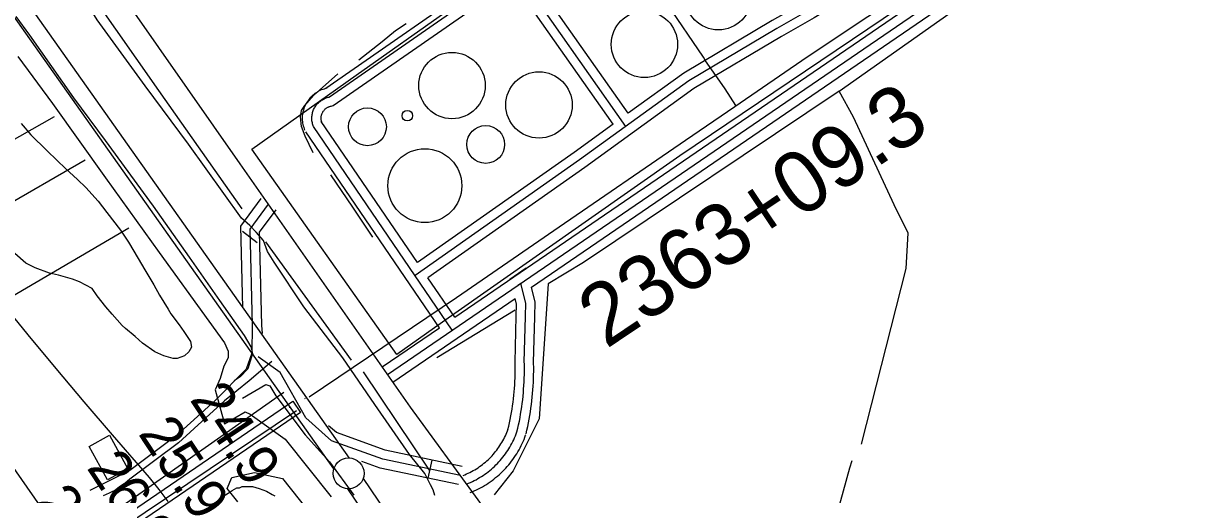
# Model space of a CAD drawing. Extents: x 3355724 to 3393621, y 594744 to 620174.
# Drawn here: x 3384041 to 3385918, y 610441 to 611204 of the extents above; entities that cross this region are included whole.
import ezdxf

# ---------------------------------------------------------------- set-up
doc = ezdxf.new("R2010")
doc.units = 0
for name, color, linetype in [('V-BLDG-OTLN', 7, 'Continuous'), ('V-CHAN-DOCK', 7, 'Continuous'), ('V-DOMW-TANK', 7, 'Continuous'), ('V-FLOD-BASE', 7, 'Continuous'), ('V-LEVE-TOET', 7, 'Continuous'), ('V-RIVR-EDGE', 7, 'Continuous'), ('V-RIVR-RANG', 7, 'Continuous'), ('V-ROAD-CNTR', 7, 'Continuous'), ('V-SITE-OTLN', 7, 'Continuous'), ('V-SITE-VEGE', 7, 'Continuous'), ('V-SURV-IDEN', 7, 'Continuous'), ('V-SURV-LINE', 7, 'Continuous'), ('V-TOPO-MAJR', 7, 'Continuous'), ('V-TOPO-SHOR', 7, 'Continuous'), ('V-UTIL-LINE', 7, 'Continuous'), ('V-WETL-SWMP', 7, 'Continuous')]:
    doc.layers.add(name, color=color, linetype=linetype)

msp = doc.modelspace()

# ---------------------------------------------------------------- linework, layer by layer
at = {"layer": 'V-BLDG-OTLN'}
msp.add_lwpolyline([(3384181, 610537.4), (3384210.7, 610483.3), (3384177.6, 610465.1), (3384147.9, 610519.2)], close=True, dxfattribs=at)
at = {"layer": 'V-CHAN-DOCK'}
msp.add_lwpolyline([(3383879.4, 610186.2), (3383922.8, 610214.2), (3383886.5, 610267.4), (3383918.5, 610289.2), (3383955.1, 610235.7), (3384477.5, 610592.5), (3384489.9, 610574.3), (3383836, 610127.7), (3383918.8, 610006.3), (3383927, 610011.9), (3383938.6, 609994.9), (3383928.7, 609988.1), (3383959.9, 609942.4), (3383971, 609950), (3384010.8, 609891.8), (3383999.7, 609884.3)], dxfattribs=at)
at = {"layer": 'V-DOMW-TANK'}
for centre, radius in [((3385165.5, 611247.4), 53.7), ((3385045.9, 611170.2), 53.7), ((3384734.8, 611103.6), 53.7), ((3384875.5, 611072.1), 53.7), ((3384598.1, 611036.8), 30.6), ((3384662.6, 611054.8), 8.61), ((3384789.3, 611008.2), 30.6), ((3384690.9, 610941.5), 59.8)]:
    msp.add_circle(centre, radius, dxfattribs=at)
at = {"layer": 'V-FLOD-BASE'}
for points in [[(3384029.3, 611215.1), (3384051.4, 611185), (3384122.6, 611083.5), (3384174.2, 611014.5), (3384251.5, 610908.4), (3384310, 610825.8), (3384358.7, 610755.7), (3384398.8, 610699.1), (3384409.4, 610680.5), (3384412.3, 610669.8), (3384404.7, 610644.8), (3384392.3, 610632.1), (3384382.4, 610625.5)], [(3384395.9, 610597.5), (3384433.9, 610619.9), (3384440.4, 610617.4), (3384449.8, 610601.4), (3384497.3, 610538.2), (3384536.6, 610494.4), (3384575.9, 610440.3)]]:
    msp.add_lwpolyline(points, dxfattribs=at)
at = {"layer": 'V-LEVE-TOET'}
msp.add_line((3384351.7, 610611.2), (3384366.8, 610555.8), dxfattribs=at)
for points in [[(3384706.9, 610439.9), (3384704.2, 610449.3), (3384699.8, 610457.5), (3384691.1, 610475.6), (3384666.1, 610506.4), (3384610, 610587.1), (3384558.3, 610662.9), (3384495.2, 610745.2), (3384447.3, 610817.7), (3384436.4, 610834.7), (3384429.9, 610852.8), (3384417.9, 610866), (3384408.1, 610877), (3384394.5, 610889.1), (3384308.5, 611008.8), (3384238.8, 611103.3), (3384160.9, 611209.9), (3384100.6, 611307.6), (3384038, 611388.9)], [(3384032.6, 611150.7), (3384088.7, 611074.4), (3384174.7, 610954.1), (3384261.2, 610833.3), (3384341.8, 610722.3), (3384366.8, 610687.2), (3384372.8, 610673.5), (3384372.7, 610663.1), (3384366.1, 610649.4), (3384360, 610629.2), (3384351.7, 610611.2)], [(3384366.8, 610555.8), (3384400.3, 610575.4), (3384408.5, 610571.5), (3384465.2, 610531.3), (3384539.3, 610437.9)]]:
    msp.add_lwpolyline(points, dxfattribs=at)
at = {"layer": 'V-RIVR-EDGE'}
msp.add_spline([(3384488, 609371.5), (3384468, 609400.3), (3384449.8, 609430.7), (3384446.7, 609441.6), (3384446.7, 609445.8), (3384449.8, 609449.4), (3384459, 609452.2), (3384462.2, 609453.6), (3384464.7, 609457.4), (3384464.7, 609462.4), (3384463.6, 609466.9), (3384459.8, 609472.2), (3384441.1, 609480.7), (3384422.5, 609488.9), (3384414.4, 609495.3), (3384408.7, 609501.6), (3384402.1, 609512.9), (3384392.3, 609532), (3384386.7, 609543.9), (3384376.1, 609562.3), (3384359.3, 609590.2), (3384337.5, 609625.5), (3384315.4, 609654.4), (3384293.6, 609688.7), (3384287.3, 609698.5), (3384283.8, 609710.9), (3384277.9, 609721.1), (3384265.6, 609738.4), (3384253.6, 609756.8), (3384246.6, 609768.1), (3384246.3, 609772.6), (3384246.3, 609776.5), (3384242.4, 609783.6), (3384235.1, 609798), (3384231.5, 609805.1), (3384224.9, 609816), (3384207.7, 609841.1), (3384198.5, 609854.5), (3384190.8, 609866.9), (3384180.7, 609885.2), (3384172.6, 609897.2), (3384163.8, 609910.6), (3384162.1, 609915.9), (3384159.6, 609926.1), (3384156.5, 609933.9), (3384148.7, 609945.9), (3384136.8, 609963.9), (3384088.7, 610023.2), (3384052.1, 610069.5), (3384015.3, 610119.2), (3383995.6, 610145.4), (3383986.1, 610157.7), (3383981.2, 610168.7), (3383979.1, 610182.8), (3383978.5, 610198.6), (3383977.8, 610206.7), (3383975.7, 610221.9), (3383972.6, 610238.4), (3383967.3, 610252.9), (3383958.9, 610271.6), (3383941, 610293.5), (3383922, 610309.8), (3383902.7, 610323.9), (3383894.2, 610334.8), (3383878.8, 610353.2), (3383873.5, 610361.7), (3383870.7, 610372.2), (3383868.3, 610388.1), (3383866.9, 610394.1), (3383863.4, 610403.3), (3383845.5, 610426.2), (3383823.3, 610446.4), (3383814.2, 610458.7), (3383797.7, 610478.8), (3383775.2, 610500.7), (3383748.1, 610529), (3383721.1, 610558.3), (3383710.5, 610571.7), (3383704.9, 610579.5), (3383693, 610606.3), (3383683.5, 610626.8), (3383664.6, 610666.6), (3383634.8, 610729.8), (3383616.2, 610766.1), (3383600.8, 610792.9)], degree=3, dxfattribs=at)
at = {"layer": 'V-ROAD-CNTR'}
for p, q in [((3384419.9, 610849.2), (3384395.8, 610867.1)), ((3384497, 610597.1), (3384497.8, 610597.5)), ((3384471.6, 610582.8), (3384472, 610583)), ((3384696.3, 610468.1), (3384702.5, 610497.4))]:
    msp.add_line(p, q, dxfattribs=at)
for points in [[(3385398.9, 609542.3), (3385133.9, 609925.7), (3385002.2, 610111.9), (3384892.4, 610269.5), (3384777.3, 610432.8), (3384667.5, 610583.2), (3384392.1, 610976.7), (3383958.2, 611597.8), (3383762.4, 611871.6), (3383538.2, 612187.4), (3383277.9, 612554.1), (3382922.5, 613059.3), (3382670, 613416.6), (3382435.3, 613754.7), (3382276.6, 613979.4), (3382102.9, 614235.8), (3381961, 614438.8), (3381786.9, 614698.7)], [(3384630.6, 610636), (3387016, 612269.2), (3387921, 612884.9), (3389025.3, 613640.7), (3389125.7, 613727.5)], [(3388670.9, 613535.3), (3385357.8, 611252.6), (3385313, 611226.2), (3385260.2, 611196), (3385117.8, 611111.2), (3384941.1, 610983.2), (3384675.1, 610796)], [(3384536.8, 611085.1), (3385903.8, 612036.2), (3386441.5, 612400), (3386654.5, 612543), (3387141, 612886.2)], [(3387329.9, 612593.1), (3385365.9, 611239.9), (3385320.6, 611213.2), (3385267.8, 611183.1), (3385126, 611098.6), (3384949.8, 610971), (3384695.8, 610792.3)], [(3384739.2, 610728.5), (3387007.5, 612281.6), (3387373.9, 612530.9)], [(3384863.1, 610777), (3387024.4, 612256.8), (3387396.9, 612510.2)], [(3384530.8, 611099.2), (3385077.4, 611479.5)], [(3385016.1, 611037.5), (3384836.5, 611293.6)], [(3385019.7, 611058.6), (3384857.5, 611289.9)], [(3384542.8, 611071), (3384832.8, 611272.8)], [(3384995.4, 611041), (3384832.8, 611272.8)], [(3385274.5, 611221.5), (3385252.6, 611209), (3385109.5, 611123.7), (3385019.7, 611058.6)], [(3384497, 611031.5), (3384496.3, 611033.4), (3384495.5, 611035.6), (3384494.8, 611037.9), (3384494.3, 611040.3), (3384493.8, 611042.6), (3384493.5, 611045), (3384493.3, 611047.4), (3384493.2, 611049.8), (3384493.2, 611052.1), (3384493.3, 611054.5), (3384493.6, 611056.9), (3384493.9, 611059.3), (3384494.4, 611061.6), (3384495, 611063.9), (3384495.7, 611066.2), (3384496.5, 611068.5), (3384497.4, 611070.7), (3384498.4, 611072.9), (3384499.5, 611075), (3384500.7, 611077), (3384502, 611079), (3384503.4, 611081), (3384504.9, 611082.8), (3384506.5, 611084.6), (3384508.2, 611086.4), (3384509.9, 611088), (3384511.8, 611089.5), (3384513.7, 611091), (3384515.6, 611092.4), (3384517.6, 611093.6), (3384519.7, 611094.8), (3384521.9, 611095.9), (3384524, 611096.9), (3384526.3, 611097.7), (3384528.5, 611098.5), (3384530.8, 611099.1), (3384533.1, 611099.6), (3384530.8, 611099.2)], [(3384511, 611037), (3384510.3, 611038.5), (3384509.8, 611040.1), (3384509.3, 611041.7), (3384509, 611043.4), (3384508.6, 611045), (3384508.4, 611046.7), (3384508.3, 611048.3), (3384508.2, 611050), (3384508.2, 611051.7), (3384508.3, 611053.4), (3384508.5, 611055), (3384508.7, 611056.7), (3384509, 611058.3), (3384509.5, 611060), (3384509.9, 611061.6), (3384510.5, 611063.1), (3384511.1, 611064.7), (3384511.8, 611066.2), (3384512.6, 611067.7), (3384513.5, 611069.1), (3384514.4, 611070.5), (3384515.4, 611071.9), (3384516.4, 611073.2), (3384517.5, 611074.4), (3384518.7, 611075.6), (3384519.9, 611076.8), (3384521.2, 611077.9), (3384522.5, 611078.9), (3384523.9, 611079.9), (3384525.3, 611080.7), (3384526.8, 611081.6), (3384528.3, 611082.3), (3384529.8, 611083), (3384531.4, 611083.6), (3384532.9, 611084.1), (3384534.6, 611084.6), (3384536.2, 611085), (3384536.8, 611085.1)], [(3384524.9, 611042.5), (3384524.4, 611043.7), (3384524.1, 611044.6), (3384523.9, 611045.5), (3384523.6, 611046.5), (3384523.5, 611047.4), (3384523.3, 611048.4), (3384523.2, 611049.3), (3384523.2, 611050.3), (3384523.2, 611051.2), (3384523.3, 611052.2), (3384523.4, 611053.1), (3384523.5, 611054.1), (3384523.7, 611055), (3384523.9, 611056), (3384524.2, 611056.9), (3384524.5, 611057.8), (3384524.9, 611058.7), (3384525.3, 611059.5), (3384525.7, 611060.4), (3384526.2, 611061.2), (3384526.7, 611062), (3384527.3, 611062.8), (3384527.9, 611063.5), (3384528.5, 611064.3), (3384529.2, 611064.9), (3384529.9, 611065.6), (3384530.6, 611066.2), (3384531.4, 611066.8), (3384532.2, 611067.3), (3384533, 611067.9), (3384533.8, 611068.3), (3384534.7, 611068.8), (3384535.6, 611069.1), (3384536.4, 611069.5), (3384537.4, 611069.8), (3384538.3, 611070.1), (3384539.3, 611070.3), (3384542.8, 611071)], [(3384678.9, 610817.1), (3384523.4, 611045.4)], [(3384714.4, 610711.6), (3384498.6, 611028.5)], [(3384735.3, 610707.6), (3384511, 611037)], [(3384995.4, 611041), (3384932.4, 610995.4), (3384678.9, 610817.1)], [(3384437.7, 610911.5), (3384407.8, 610871.3), (3384411.9, 610715.6), (3384410.9, 610670.4), (3384401.8, 610644.4), (3384351.6, 610593.8), (3384289.1, 610537.1), (3384214.1, 610480.7), (3384149.4, 610448.1)], [(3384425.7, 610920.5), (3384392.7, 610876.1), (3384396.2, 610744)], [(3384449.7, 610902.6), (3384422.9, 610866.5), (3384426.9, 610715.7), (3384427.6, 610702.1)], [(3384855, 610807.8), (3384828.2, 610789.5)], [(3384739.2, 610728.5), (3384695.8, 610792.3)], [(3384851.7, 610655.6), (3384853.8, 610729.7), (3384854.3, 610751.3), (3384845.9, 610783.4), (3384841.1, 610780.1)], [(3384866.7, 610655.2), (3384868.8, 610729.3), (3384869.4, 610753), (3384863.1, 610777)], [(3384639.1, 610623.6), (3384836.8, 610759)], [(3384836.7, 610656), (3384838.8, 610730.1), (3384839.3, 610749.5), (3384836.8, 610759)], [(3384622.1, 610648.3), (3384714.4, 610711.6)], [(3384443.3, 610657), (3384406.6, 610625.8), (3384367.1, 610593.1), (3384337, 610565.5), (3384292.3, 610525.5), (3384213.9, 610466.7), (3384210.2, 610463.2), (3384206.3, 610459.9), (3384202.2, 610456.7), (3384198.1, 610453.7), (3384193.8, 610450.9), (3384189.4, 610448.3), (3384184.8, 610445.8), (3384180.2, 610443.6), (3384175.5, 610441.5), (3384170.8, 610439.6)], [(3384748.4, 610472.5), (3384622.9, 610498.8), (3384540, 610528.6), (3384498.5, 610565.8), (3384456.9, 610639.3), (3384421.2, 610664.3)], [(3384825.3, 610546.6), (3384826.6, 610552.2), (3384827.8, 610557.7), (3384829, 610563.2), (3384830, 610568.8), (3384831, 610574.3), (3384831.9, 610579.9), (3384832.8, 610585.4), (3384833.5, 610591), (3384834.2, 610596.6), (3384834.8, 610602.2), (3384835.3, 610607.8), (3384835.8, 610613.4), (3384836.2, 610619), (3384836.5, 610624.6), (3384836.7, 610630.3), (3384836.8, 610635.9), (3384836.9, 610641.5), (3384836.9, 610647.2), (3384836.8, 610652.8), (3384836.7, 610655.2)], [(3384839.9, 610543.2), (3384841.2, 610548.9), (3384842.5, 610554.6), (3384843.7, 610560.3), (3384844.8, 610566), (3384845.8, 610571.8), (3384846.8, 610577.5), (3384847.6, 610583.3), (3384848.4, 610589.1), (3384849.1, 610594.9), (3384849.7, 610600.7), (3384850.3, 610606.5), (3384850.7, 610612.3), (3384851.1, 610618.1), (3384851.4, 610624), (3384851.7, 610629.8), (3384851.8, 610635.6), (3384851.9, 610641.5), (3384851.9, 610647.3), (3384851.8, 610653.1), (3384851.7, 610655.6)], [(3384854.5, 610539.8), (3384855.9, 610545.6), (3384857.2, 610551.5), (3384858.4, 610557.4), (3384859.5, 610563.3), (3384860.6, 610569.3), (3384861.6, 610575.2), (3384862.5, 610581.2), (3384863.3, 610587.2), (3384864, 610593.2), (3384864.7, 610599.2), (3384865.2, 610605.2), (3384865.7, 610611.2), (3384866.1, 610617.2), (3384866.4, 610623.3), (3384866.7, 610629.3), (3384866.8, 610635.3), (3384866.9, 610641.4), (3384866.9, 610647.4), (3384866.8, 610653.4), (3384866.7, 610656)], [(3384751.4, 610487.2), (3384627, 610513.3), (3384547.8, 610541.8), (3384535.3, 610552.9)], [(3384752.8, 610472.5), (3384755.8, 610473.7), (3384758.5, 610474.9), (3384761.2, 610476.2), (3384763.9, 610477.5), (3384766.6, 610478.9), (3384769.2, 610480.3), (3384771.8, 610481.8), (3384774.3, 610483.4), (3384776.9, 610485), (3384779.3, 610486.7), (3384781.8, 610488.5), (3384784.1, 610490.3), (3384786.5, 610492.1), (3384788.8, 610494), (3384791, 610496), (3384793.2, 610498), (3384795.4, 610500.1), (3384797.5, 610502.2), (3384799.6, 610504.4), (3384801.6, 610506.6), (3384803.5, 610508.9), (3384805.4, 610511.2), (3384807.2, 610513.6), (3384809, 610516), (3384810.7, 610518.5), (3384812.4, 610520.9), (3384814, 610523.5), (3384815.5, 610526), (3384817, 610528.6), (3384818.4, 610531.3), (3384819.8, 610533.9), (3384821.1, 610536.6), (3384822.3, 610539.4), (3384823.5, 610542.1), (3384824.6, 610544.9), (3384825.6, 610547.8), (3384825.8, 610548.2)], [(3384758.5, 610458.6), (3384761.6, 610459.9), (3384764.7, 610461.2), (3384767.7, 610462.6), (3384770.7, 610464.1), (3384773.7, 610465.6), (3384776.6, 610467.3), (3384779.5, 610468.9), (3384782.4, 610470.7), (3384785.2, 610472.5), (3384787.9, 610474.4), (3384790.7, 610476.4), (3384793.3, 610478.4), (3384796, 610480.5), (3384798.5, 610482.6), (3384801.1, 610484.8), (3384803.5, 610487.1), (3384805.9, 610489.4), (3384808.3, 610491.8), (3384810.6, 610494.3), (3384812.8, 610496.7), (3384815, 610499.3), (3384817.1, 610501.9), (3384819.2, 610504.5), (3384821.2, 610507.2), (3384823.1, 610510), (3384825, 610512.8), (3384826.8, 610515.6), (3384828.5, 610518.5), (3384830.2, 610521.4), (3384831.7, 610524.3), (3384833.3, 610527.3), (3384834.7, 610530.3), (3384836.1, 610533.4), (3384837.4, 610536.5), (3384838.6, 610539.6), (3384839.8, 610542.8), (3384839.9, 610543.2)], [(3384764.1, 610444.7), (3384767.4, 610446), (3384770.8, 610447.5), (3384774.2, 610449.1), (3384777.5, 610450.7), (3384780.8, 610452.4), (3384784, 610454.2), (3384787.2, 610456.1), (3384790.4, 610458), (3384793.5, 610460.1), (3384796.6, 610462.1), (3384799.6, 610464.3), (3384802.5, 610466.5), (3384805.4, 610468.9), (3384808.3, 610471.2), (3384811.1, 610473.7), (3384813.8, 610476.2), (3384816.5, 610478.8), (3384819.1, 610481.4), (3384821.6, 610484.1), (3384824.1, 610486.9), (3384826.5, 610489.7), (3384828.9, 610492.5), (3384831.1, 610495.5), (3384833.3, 610498.5), (3384835.5, 610501.5), (3384837.5, 610504.6), (3384839.5, 610507.7), (3384841.4, 610510.9), (3384843.3, 610514.1), (3384845, 610517.4), (3384846.7, 610520.7), (3384848.3, 610524), (3384849.8, 610527.4), (3384851.3, 610530.8), (3384852.6, 610534.3), (3384853.9, 610537.7), (3384854.1, 610538.3)], [(3384745.3, 610457.8), (3384618.8, 610484.4), (3384588.9, 610495.1)]]:
    msp.add_lwpolyline(points, dxfattribs=at)
at = {"layer": 'V-SITE-OTLN'}
for p, q in [((3385990.6, 611589.1), (3385103.3, 610989.9)), ((3384579.9, 611120.1), (3384732.4, 611228.1)), ((3384411.4, 611000.7), (3384579.9, 611120.1)), ((3384645.5, 610668.4), (3384411.4, 611000.7)), ((3385103.3, 610989.9), (3384728.8, 610726.9)), ((3384728.8, 610726.9), (3384645.5, 610668.4))]:
    msp.add_line(p, q, dxfattribs=at)
at = {"layer": 'V-SITE-VEGE'}
for points in [[(3384038.2, 611042), (3384054, 611023.9), (3384079.4, 610998.3), (3384096.3, 610982.3), (3384110.1, 610969.5), (3384129.1, 610951.4), (3384142.9, 610938.6), (3384162.9, 610916.2), (3384176.7, 610898.1), (3384198.9, 610869.3), (3384211.5, 610850.2), (3384227.3, 610823.6), (3384237.9, 610805.5), (3384252.6, 610781), (3384262.1, 610764), (3384275.8, 610741.6), (3384280, 610734.2), (3384293.8, 610716.1), (3384301.1, 610705.4), (3384311.7, 610689.4), (3384313.8, 610679.9), (3384309.5, 610672.5), (3384302, 610666.1), (3384290.3, 610661.9), (3384284, 610661.9), (3384269.1, 610666.3), (3384254.3, 610672.7), (3384234.2, 610686.6), (3384222.5, 610697.2), (3384206.7, 610710.1), (3384201.4, 610715.4), (3384185.5, 610733.5), (3384175, 610745.2), (3384161.2, 610763.3), (3384152.8, 610775), (3384132.7, 610785.7), (3384121, 610790), (3384098.7, 610796.5), (3384083.9, 610799.8), (3384060.6, 610808.3), (3384045.7, 610815.8), (3384027.8, 610831.8)], [(3384358.1, 610434.5), (3384373, 610444), (3384379.4, 610448.2), (3384386.8, 610452.4), (3384391, 610452.4), (3384395.3, 610454.5), (3384412.3, 610454.4), (3384422.9, 610451.2), (3384434.6, 610446.9), (3384444.1, 610441.6), (3384448.3, 610439.4)]]:
    msp.add_lwpolyline(points, dxfattribs=at)
at = {"layer": 'V-SURV-LINE'}
for points in [[(3381657.4, 614621.7), (3384568.3, 610500.7)], [(3384543.8, 610483.4), (3381632.9, 614604.4)], [(3384591.2, 610467.6), (3385264.4, 609472.1)], [(3385239.6, 609455.3), (3384566.3, 610450.8)]]:
    msp.add_lwpolyline(points, dxfattribs=at)
msp.add_circle((3384567.6, 610475.8), 25, dxfattribs=at)
at = {"layer": 'V-TOPO-MAJR'}
for points in [[(3384004.6, 610754.7), (3384049.1, 610700), (3384094, 610645.6), (3384139.5, 610591.8), (3384185.4, 610538.2), (3384245.3, 610469.1), (3384260.9, 610449.9), (3384275.5, 610430.1)], [(3384115.6, 610356.1), (3383877, 610698.2)]]:
    msp.add_lwpolyline(points, dxfattribs=at)
at = {"layer": 'V-TOPO-SHOR'}
for p, q in [((3384572.4, 610659.2), (3384433.9, 610850.5)), ((3384710.4, 610663.4), (3384836.7, 610740.4)), ((3384699.4, 610479.3), (3384591.7, 610640.1))]:
    msp.add_line(p, q, dxfattribs=at)
for points in [[(3384395.5, 610904), (3384260.8, 611095.3), (3383941.5, 611550.7), (3383683.7, 611921.8), (3383375.9, 612338.8), (3382995, 612893.6)], [(3385396.9, 610523.3), (3385469, 610807.2), (3385472.7, 610864.7), (3385449.6, 610910.6), (3385384.1, 611052.3), (3385360.9, 611094.4), (3385635.2, 611288.8)], [(3384584.3, 611145.4), (3384621.9, 611174.7), (3384643.2, 611192.6), (3384660.7, 611203.9)], [(3384510.1, 610994.7), (3384497.4, 611021.4), (3384491.6, 611037.3), (3384489.6, 611052.9), (3384491.7, 611062.9), (3384496.7, 611071.1), (3384510.9, 611087.2), (3384550.3, 611122.5)], [(3385360.9, 611094.4), (3384947.7, 610817.3), (3384890.3, 610782.7), (3384875.5, 610564.1), (3384833.6, 610479.7), (3384803, 610441.3)], [(3384606.7, 610858), (3384574.3, 610906.9), (3384538.7, 610958.8)], [(3385206.5, 610074.3), (3385279.2, 610124.4), (3385377.9, 610485), (3385381.7, 610496.5)]]:
    msp.add_lwpolyline(points, dxfattribs=at)
at = {"layer": 'V-UTIL-LINE'}
for p, q in [((3380891.1, 609237.5), (3384091.8, 611053.6)), ((3380941.2, 609137.2), (3384141.9, 610983.4)), ((3381001.4, 608996.7), (3384212.2, 610873))]:
    msp.add_line(p, q, dxfattribs=at)
for points in [[(3385192, 611069.8), (3385309.2, 611149.8), (3385505.1, 611281.4), (3385689.3, 611411.8), (3385943, 611587.8)], [(3385194, 611071.2), (3385176.5, 611098.3), (3385167.7, 611110.7), (3385144.9, 611143.8), (3385141.4, 611149.7), (3385082.9, 611235.8), (3385077.1, 611245.8), (3385028.5, 611317.2)], [(3384503.8, 610599.6), (3384742.2, 610760.4), (3384742.2, 610760.4), (3384908, 610875), (3385112.2, 611015.3), (3385192, 611069.8)], [(3383945.2, 610250.8), (3384213.9, 610432.1), (3384462.9, 610607)], [(3384483.2, 610577), (3384028.6, 610270.9), (3383830.8, 610129.3)]]:
    msp.add_lwpolyline(points, dxfattribs=at)
at = {"layer": 'V-WETL-SWMP'}
msp.add_lwpolyline([(3384388.5, 610429.6), (3384371.2, 610451.6), (3384378.6, 610469.3), (3384415.2, 610477.4), (3384460.8, 610467.6), (3384502.2, 610415.4)], dxfattribs=at)

# ---------------------------------------------------------------- texts
at = {"layer": 'V-RIVR-RANG'}
for s, p in [('24.9', (3384309.7, 610595.6)), ('25.9', (3384226.3, 610540.4)), ('26.9', (3384143, 610485.1)), ('29.3', (3384059.8, 610429.6))]:
    msp.add_text(s, height=67, rotation=303.4083, dxfattribs=at).set_placement(p)
at = {"layer": 'V-SURV-IDEN'}
msp.add_text('2363+09.3', height=100, rotation=33.9044, dxfattribs=at).set_placement((3384984.1, 610676.4))

doc.saveas('drawing.dxf')
